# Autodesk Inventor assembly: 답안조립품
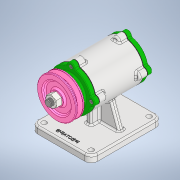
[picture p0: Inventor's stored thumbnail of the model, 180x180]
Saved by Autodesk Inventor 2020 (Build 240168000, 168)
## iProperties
Created: 2022-11
Part Number: 답안조립품
Document SubType Name: Assembly
Designer: owner
Author: owner
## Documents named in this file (12)
- C:\Users\owner\Desktop\721108V1011\답안조립품.iam
- C:\Users\owner\Desktop\721108V1011\본체.ipt
- C:\Users\owner\Desktop\721108V1011\앞커버.ipt
- C:\Users\owner\Desktop\721108V1011\오일 실.ipt
- C:\Users\owner\Desktop\721108V1011\축.ipt
- C:\Users\owner\Desktop\721108V1011\키 4 x 4.ipt
- C:\Users\owner\Desktop\721108V1011\V-벨트풀리.ipt
- C:\Users\owner\Desktop\721108V1011\개스킷.ipt
- C:\Users\owner\Desktop\721108V1011\너트 M12 x 1.25.ipt
- C:\Users\owner\Desktop\721108V1011\뒤커버.ipt
- C:\Users\owner\Desktop\721108V1011\베어링 6204.ipt
- C:\Users\owner\Desktop\721108V1011\볼트 M4 x 12.ipt
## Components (8 placed, 6 different names)
1. KS B 2804 D D - 20 32 8:1
2. KS B 1311 (I) 4 x 4 x 12:1
3. V-벨트풀리:1 — 각도:1
4. 개스킷:1
5. KS B 1012 클래스 1 일반 - 미터 M12x1.25:1 — 각도:1
6. KS B 2023 6204 - 20 x 47 x 14:1
7. KS B 2023 6204 - 20 x 47 x 14:2
8. 개스킷:2
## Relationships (1: Angle 1)
- 각도:1 [Angle]: V-벨트풀리:1 ↔ KS B 1012 클래스 1 일반 - 미터 M12x1.25:1
